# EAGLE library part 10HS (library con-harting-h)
CONNECTOR
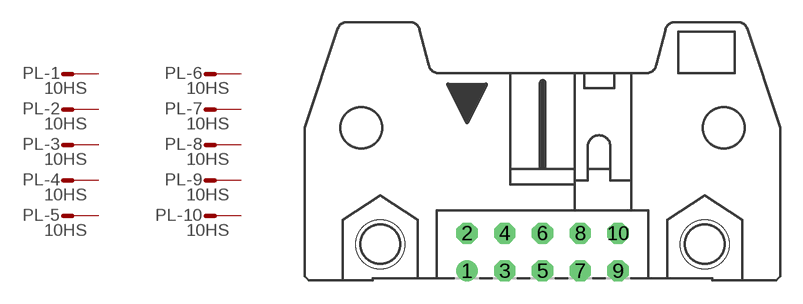
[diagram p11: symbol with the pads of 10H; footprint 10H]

Designator prefix PL; gates -1=M -2=M -3=M -4=M -5=M -6=M -7=M -8=M -9=M -10=M

## 10HS (OC_FARNELL: unknown; OC_NEWARK: unknown)  [10H]
1  -1:S  pas
2  -2:S  pas
3  -3:S  pas
4  -4:S  pas
5  -5:S  pas
6  -6:S  pas
7  -7:S  pas
8  -8:S  pas
9  -9:S  pas
10  -10:S  pas

## Footprint 10H (pad centres in mm)
CONNECTOR
drill 0.914 round: 1 -5.08,-1.27
drill 0.914 octagon: 2 -5.08,1.27; 3 -2.54,-1.27; 4 -2.54,1.27; 5 0,-1.27; 6 0,1.27; 7 2.54,-1.27; 8 2.54,1.27; 9 5.08,-1.27; 10 5.08,1.27
hole 3.302 at -10.922,0.533
hole 3.302 at 10.922,0.533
